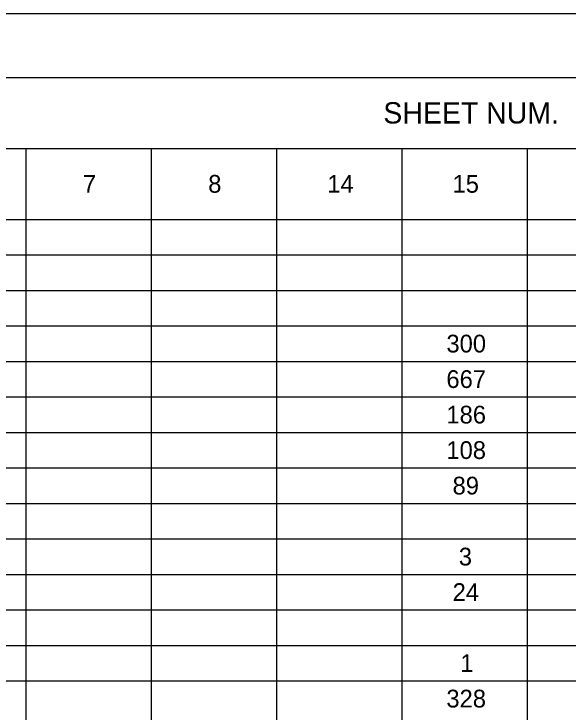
# Model space of a CAD drawing. Extents: x 0 to 34, y 0 to 22.
# Drawn here: x 4.37 to 8.74, y 16.49 to 22 of the extents above; entities that cross this region are included whole.
import ezdxf

# ---------------------------------------------------------------- set-up
doc = ezdxf.new("R2010")
doc.units = 0
for name, color, linetype in [('Default', 7, 'Continuous'), ('SH_Border', 7, 'Continuous'), ('SH_Cut_Line', 7, 'Continuous')]:
    doc.layers.add(name, color=color, linetype=linetype)

msp = doc.modelspace()

# ---------------------------------------------------------------- linework, layer by layer
at = {"layer": 'Default'}
for p, q in [((1.5, 21.5), (31.68951, 21.5)), ((1.5, 20.94002), (15.3348, 20.94002)), ((4.4646, 20.94002), (4.4646, 0.50075)), ((5.4528, 20.94002), (5.4528, 0.50075)), ((6.441, 20.94002), (6.441, 0.50075)), ((7.4292, 20.94002), (7.4292, 0.50075)), ((8.4174, 20.94002), (8.4174, 0.50075)), ((1.5, 20.38004), (31.68951, 20.38004)), ((1.5, 20.10005), (31.68951, 20.10005)), ((1.5, 19.82006), (31.68951, 19.82006)), ((1.5, 19.54007), (31.68951, 19.54007)), ((1.5, 19.26008), (31.68951, 19.26008)), ((1.5, 18.98009), (31.68951, 18.98009)), ((1.5, 18.7001), (31.68951, 18.7001)), ((1.5, 18.42011), (31.68951, 18.42011)), ((1.5, 18.14012), (31.68951, 18.14012)), ((1.5, 17.86013), (31.68951, 17.86013)), ((1.5, 17.58014), (31.68951, 17.58014)), ((1.5, 17.30015), (31.68951, 17.30015)), ((1.5, 17.02016), (31.68951, 17.02016)), ((1.5, 16.74017), (31.68951, 16.74017))]:
    msp.add_line(p, q, dxfattribs=at)
at = {"layer": 'SH_Border'}
msp.add_lwpolyline([(1.5, 21.5), (33.5, 21.5), (33.5, 0.5), (1.5, 0.5)], close=True, dxfattribs=at)
at = {"layer": 'SH_Cut_Line'}
msp.add_lwpolyline([(0, 0), (34, 0), (34, 22), (0, 22)], close=True, dxfattribs=at)

# ---------------------------------------------------------------- texts
at = {"layer": 'Default'}
for s, height, p in [('SHEET NUM.', 0.168, (7.282947, 21.13601)), ('7', 0.14, (4.913755, 20.59003)), ('8', 0.14, (5.901859, 20.59003)), ('14', 0.14, (6.841512, 20.59003)), ('15', 0.14, (7.828944, 20.59003)), ('300', 0.14, (7.780734, 19.330075)), ('667', 0.14, (7.780494, 19.050085)), ('186', 0.14, (7.780494, 18.770095)), ('108', 0.14, (7.780398, 18.490105)), ('89', 0.14, (7.829328, 18.210115)), ('3', 0.14, (7.878355, 17.650135)), ('24', 0.14, (7.829712, 17.370145)), ('1', 0.14, (7.890552, 16.810165)), ('328', 0.14, (7.780398, 16.530175))]:
    msp.add_text(s, height=height, dxfattribs=at).set_placement(p)

doc.saveas('drawing.dxf')
